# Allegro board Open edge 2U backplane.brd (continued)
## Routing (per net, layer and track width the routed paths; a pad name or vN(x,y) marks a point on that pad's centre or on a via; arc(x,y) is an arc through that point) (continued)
SMB_SLED_COMBINE_SCL_R1: length 15.9
  TOP w0.114: R4.2 167.08,25.94 v1(167.58,25.44)
  IN2 w0.127: v1(167.58,25.44) 168.08,25.94 170.46,25.94 171.54,27.02 179.21,27.02 179.98,27.79 J8.G5
SMB_SLED_COMBINE_SDA: length 149.5
  TOP w0.114: v1(34.53,30.39) 33.08,28.94 33.08,21.74 R1122.2 ; R5.1 164.46,27.03 v1(163.5,27.99) ; R47.1 v1(153.02,31.64)
  IN1 w0.127: v1(34.53,30.39) 35.42,31.28 35.42,32.95 38.78,36.31 147.69,36.31 152.35,31.64 v1(153.02,31.64)
  IN2 w0.127: v1(153.02,31.64) 153.37,31.3 160.2,31.3 v1(163.5,27.99)
SMB_SLED_COMBINE_SDA_R: length 4.5
  TOP w0.114: R49.2 R47.2 154.69,30.77 155.6,30.77 156.29,30.08 U118.6
SMB_SLED_COMBINE_SDA_R1: length 16.1
  TOP w0.114: R5.2 166.8,27.03 167.26,27.49 v1(167.7,27.49)
  IN2 w0.127: J8.H5 180.27,29.19 179.66,29.79 171.6,29.79 169.31,27.49 v1(167.7,27.49)
TMP75_1_A0: length 5.9
  TOP w0.114: U31.7 38.91,27.21 v3(38.13,27.98) 37.84,28.28 R1114.1 R1113.2
TMP75_1_A1: length 5.4
  TOP w0.114: U31.6 v3(40.18,27.72) 40.18,29.69 R1108.2 R1109.1
TMP75_1_A2: length 6.1
  TOP w0.114: U31.5 41.45,26.4 42.31,27.27 42.31,28.42 41.59,29.15 R1102.2 R1103.1
TP_BUF_EN: length 4.4
  TOP w0.114: 154.42,33.64 155.29,32.77 155.29,32.01 156.49,30.81 U118.5
TP_FM_BMC_SLED4_READY_N: length 5.3
  BOTTOM w0.114: v2(176.91,38.11) 177.62,37.4 177.62,34.1 J8.K3
TP_FM_BMC_SLED5_READY_N: length 9.5
  BOTTOM w0.114: v2(195.35,32.52) 190.46,32.52 189.89,31.95 189.89,31.52 189.6,31.23 188.43,31.23 187.68,30.49 J8.I8
TP_FM_SLED4_PRSNT_N: length 9.5
  BOTTOM w0.114: J8.J3 177.6,31.98 177.89,32.27 177.89,37.26 178.73,38.11 v2(180.91,38.11)
TP_FM_SLED5_PRSNT_N: length 8.4
  BOTTOM w0.114: v2(194.01,30.51) 193.32,31.2 190.13,31.2 189.76,30.84 189.76,30.6 189.11,29.95 188.23,29.95 187.37,29.09 J8.H8
TP_LAN_SLED4_MDIN0: length 3.2
  BOTTOM w0.114: J8.H1 170.06,29.19 v2(169.79,29.46)
TP_LAN_SLED4_MDIN1: length 3
  BOTTOM w0.114: J8.K1 v2(169.91,33.38)
TP_LAN_SLED4_MDIN2: length 9.1
  TOP w0.114: v3(169.44,35.64) 170.5,35.64 171.69,34.44 171.69,31.92 172.29,31.32 174.06,31.32 J8.I2
TP_LAN_SLED4_MDIN3: length 6.8
  TOP w0.114: J8.L2 171.62,37.97 v3(169.45,37.97)
TP_LAN_SLED4_MDIP0: length 3.2
  BOTTOM w0.114: J8.G1 171.8,27.79 171.61,27.59 v2(169.79,27.59)
TP_LAN_SLED4_MDIP1: length 3.2
  BOTTOM w0.114: v2(169.89,31.41) 170.46,31.98 J8.J1
TP_LAN_SLED4_MDIP2: length 8.1
  TOP w0.114: J8.H2 174.09,29.9 172.03,29.9 171.09,30.84 171.09,31.98 v3(169.4,33.66)
TP_LAN_SLED4_MDIP3: length 9.3
  TOP w0.114: J8.K2 174,34.19 174,34.83 171.9,36.93 v3(167.44,36.93)
TP_LAN_SLED5_MDIN0: length 13.2
  IN1 w0.127: J8.K5 179.87,33.38 179.27,33.99 172.13,33.99 171.32,34.79 169.11,34.79 v1(168.54,34.22)
TP_LAN_SLED5_MDIN1: length 20.4
  BOTTOM w0.114: v2(200.51,36.24) 199.18,37.57 186.39,37.57 183.77,34.95 183.77,34.15 J8.K6
TP_LAN_SLED5_MDIN2: length 16.7
  BOTTOM w0.114: J8.K7 185.67,34.16 185.67,36.04 186.93,37.3 197.43,37.3 v2(198.47,36.27)
TP_LAN_SLED5_MDIN3: length 10.8
  BOTTOM w0.114: J8.L8 189.25,37.04 195.74,37.04 v2(196.45,36.33)
TP_LAN_SLED5_MDIP0: length 13.7
  IN1 w0.127: J8.J5 180.13,31.98 179.52,32.59 v1(167.45,32.59)
TP_LAN_SLED5_MDIP1: length 17.7
  IN1 w0.127: v1(166.29,34.62) 167.1,35.43 179.17,35.43 180.48,34.13 181.38,34.13 181.93,34.68 J8.L6
TP_LAN_SLED5_MDIP2: length 11.9
  BOTTOM w0.114: J8.J7 185.81,31.98 186.4,32.57 187.58,32.57 187.98,32.96 187.98,33.82 188.29,34.14 189.57,34.14 189.98,34.55 189.98,35.19 190.28,35.49 192.72,35.49 v2(193.95,34.26)
TP_LAN_SLED5_MDIP3: length 9.2
  BOTTOM w0.114: J8.K8 186.9,33.28 187.88,34.27 187.88,35.15 189.5,36.77 193.23,36.77 v2(193.84,36.16)
TP_TMP75_1_ALERT: length 5.1
  TOP w0.114: U31.3 40.18,19.46 40.89,18.74 v1(44.39,18.74)

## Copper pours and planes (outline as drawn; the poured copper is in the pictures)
GND on TOP (solid shape): 244.9,2.05 236.9,2.05 236.9,4.05 244.9,4.05
GND on TOP (solid shape): 36.08,65.24 36.58,65.24 36.58,65.24 37.26,65.24 37.36,65.15 37.36,47.64 37.18,47.46 32.37,47.46 31.75,48.08 31.75,64.66 32.33,65.24 36.08,65.24
GND on TOP (solid shape): 149.84,10.79 152.29,10.79 152.36,10.73 157.64,10.73 157.7,10.79 160.85,10.79 160.85,10.29 149.82,10.29 149.48,10.43 149.34,10.77 149.34,17.8 118.06,17.8 118.06,18.31 149.84,18.31
GND on TOP (solid shape): 164.76,37.7 164.76,33.98 164.59,33.81 156.71,33.81 156.65,33.87 156.65,34.79 156.54,34.9 153.42,34.9 150.85,32.34 150.85,32.33 150.56,32.04 150.56,30.84 150.18,30.46 150.17,30.45 149.95,30.32 149.87,30.08 149.98,29.81 150.25,29.7 150.33,29.71 150.42,29.74 150.51,29.73 150.56,29.65 150.56,18.66 149.81,17.91 144.17,17.91 144.01,18.06 144.01,37.47 144.81,38.26 164.2,38.26
GND on TOP (solid shape): 171.34,18.17 192.08,18.17 192.21,18.3 194.87,18.3 194.87,10.79 201.69,10.79 201.79,10.7 207.72,10.7 207.82,10.79 218.6,10.79 219.12,10.73 219.6,10.53 220.65,10.53 220.94,10.23 220.94,9.18 220.85,9.08 220.08,9.08 219.55,9.95 218.6,10.29 194.85,10.29 194.5,10.43 194.36,10.77 194.36,17.8 169.94,17.8 169.94,18.3 171.2,18.3
GND on TOP (solid shape): 256.9,72.25 256.9,2.06 256.46,1.62 249.7,1.62 249.63,1.7 249.63,29.1 252.83,33.85 249.63,38.6 249.63,72.51 249.76,72.64 256.51,72.64
GND on TOP (solid shape): outline of 303 points within 0.15,64 11.15,71.5
GND on TOP (solid shape): outline of 303 points within 32.15,11 43.15,18.5
GND on TOP (solid shape): outline of 303 points within 96.15,11 107.15,18.5
GND on TOP (solid shape): outline of 303 points within 149.15,11 160.15,18.5
GND on TOP (solid shape): outline of 303 points within 199.15,11 210.15,18.5
GND on TOP (solid shape): outline of 303 points within 220.15,64 231.15,71.5
GND on TOP (solid shape): outline of 132 points within 0.51,0.51 256.99,72.69
GND on BOTTOM (solid shape): 189.22,17.8 169.94,17.8 169.94,18.3 189.22,18.3
GND on BOTTOM (solid shape): 244.9,2.05 236.9,2.05 236.9,4.05 244.9,4.05
GND on BOTTOM (solid shape): 149.84,10.79 152.29,10.79 152.36,10.73 157.64,10.73 157.71,10.79 160.85,10.79 160.85,10.29 149.82,10.29 149.48,10.43 149.34,10.77 149.34,17.8 118.06,17.8 118.06,18.31 149.84,18.31
GND on BOTTOM (solid shape): 256.95,72.2 256.95,2.07 256.55,1.67 251.14,1.67 251.14,30.04 252.39,31.77 252.83,33.85 252.39,35.93 251.14,37.66 251.14,72.05 250.86,72.33 250.86,72.48 250.98,72.6 256.56,72.6
GND on BOTTOM (solid shape): 194.87,10.79 201.69,10.79 201.79,10.69 207.72,10.69 207.82,10.79 218.6,10.79 219.12,10.73 219.6,10.53 220.65,10.53 221.04,10.14 221.04,9.27 220.85,9.08 220.08,9.08 219.55,9.95 218.6,10.29 194.85,10.29 194.5,10.43 194.36,10.77 194.36,17.8 193.97,17.8 193.97,18.3 194.87,18.3
GND on BOTTOM (solid shape): outline of 303 points within 0.15,64 11.15,71.5
GND on BOTTOM (solid shape): outline of 303 points within 32.15,11 43.15,18.5
GND on BOTTOM (solid shape): outline of 303 points within 96.15,11 107.15,18.5
GND on BOTTOM (solid shape): outline of 303 points within 149.15,11 160.15,18.5
GND on BOTTOM (solid shape): outline of 303 points within 199.15,11 210.15,18.5
GND on BOTTOM (solid shape): outline of 303 points within 220.15,64 231.15,71.5
GND on BOTTOM (solid shape): outline of 3515 points within 0.51,0.51 256.99,72.69
GND on GND (solid shape): outline of 2466 points within 0.51,0.51 256.99,72.69
GND on IN1 (solid shape): 149.84,10.79 165.13,10.79 165.13,10.29 149.82,10.29 149.48,10.43 149.34,10.77 149.34,17.8 118.06,17.8 118.06,18.31 149.84,18.31
GND on IN1 (solid shape): 194.87,10.79 218.6,10.79 219.12,10.73 219.6,10.53 220.65,10.53 221.04,10.14 221.04,9.27 220.85,9.08 220.08,9.08 219.55,9.95 218.6,10.29 194.85,10.29 194.5,10.43 194.36,10.77 194.36,17.8 169.97,17.8 169.97,18.3 194.87,18.3
GND on IN1 (solid shape): outline of 125 points within 0.51,0.51 256.99,72.69
GND on IN1 (solid shape): outline of 2408 points within 0.64,10.39 46.58,72.59
GND on IN1 (solid shape): outline of 3747 points within 189.33,0.67 256.92,72.59
GND on IN2 (solid shape): 189.2,17.8 169.97,17.8 169.97,18.3 189.2,18.3
GND on IN2 (solid shape): 149.84,10.79 165.13,10.79 165.13,10.29 149.82,10.29 149.48,10.43 149.34,10.77 149.34,17.8 118.07,17.8 118.07,18.31 149.84,18.31
GND on IN2 (solid shape): 194.87,10.79 218.6,10.79 219.12,10.73 219.6,10.53 220.65,10.53 221.04,10.14 221.04,9.27 220.85,9.08 220.08,9.08 219.55,9.95 218.6,10.29 194.85,10.29 194.5,10.43 194.36,10.77 194.36,17.8 192.8,17.8 192.8,18.3 194.87,18.3
GND on IN2 (solid shape): 256.95,72.24 256.95,2.31 256.29,1.65 236.72,1.65 236.69,1.68 236.69,1.78 236.74,1.83 237.06,1.83 237.62,2.39 237.62,3.89 238.45,4.72 239.1,4.72 239.1,4.72 250.07,4.72 250.21,4.72 251.02,5.54 251.02,29.94 252.83,33.85 251.02,37.76 251.02,71.93 250.66,72.28 250.66,72.47 250.81,72.62 251.02,72.62 251.04,72.64 256.54,72.64
GND on IN2 (solid shape): outline of 129 points within 0.51,0.51 256.99,72.69
GND on IN2 (solid shape): outline of 7125 points within 0.57,10.35 161.7,72.58
GND on GND1 (solid shape): outline of 2466 points within 0.51,0.51 256.99,72.69
P3V3_RMC_STBY on TOP (solid shape): 166.85,33.05 166.85,32.13 166.59,31.87 166.02,31.87 165.84,32.05 165.84,32.3 165.82,32.43 165.76,32.55 165.74,32.62 165.68,32.67 165.67,32.67 165.49,32.85 163.45,32.85 162.58,31.98 162.58,31.47 162.43,31.31 161.52,31.31 161.45,31.31 161.37,31.29 160.74,31.29 160.63,31.17 160.63,29.21 160.75,29.09 161.25,29.09 161.38,29.02 161.52,28.99 162.4,28.99 162.43,28.97 162.43,27.02 162.18,26.77 161.12,26.77 161.07,26.82 161.07,27.06 161.07,27.07 161.13,27.2 161.15,27.34 161.13,27.49 161.07,27.62 161.07,27.63 161.07,27.77 160.83,28.01 157.87,28.01 157.59,27.72 157.59,27.53 157.56,27.44 157.56,27.35 157.56,27.27 157.59,27.18 157.59,27.05 157.57,27.03 157.57,26.79 157.28,26.5 154.18,26.5 153.93,26.74 153.93,28.37 154.01,28.45 156.07,28.45 156.62,28.99 157.17,28.99 157.32,29.02 157.45,29.09 157.76,29.09 157.79,29.09 157.84,29.11 158.44,29.71 158.44,31.18 158.06,31.56 156.25,31.56 155.66,32.15 155.66,33.07 156.01,33.41 166.49,33.41
P3V3_RMC_STBY on BOTTOM (solid shape): 180.27,34.87 180.27,32.82 179.9,32.46 178.43,32.46 178.22,32.67 178.22,35.12 178.38,35.29 179.85,35.29
P12V_PSU on TOP (solid shape): outline of 1544 points within 221.54,4.44 249.27,71.67
P12V_PSU on TOP (solid shape): outline of 2498 points within 21.93,18.69 143.72,66.38
P12V_PSU on BOTTOM (solid shape): outline of 1671 points within 221.47,4.61 250.75,71.87
P12V_PSU on IN1 (solid shape): outline of 1458 points within 221.47,4.86 250.27,65.18
P12V_PSU on IN1 (solid shape): outline of 2640 points within 21.21,18.6 143.94,65.03
P12V_PSU on VCC (solid shape): outline of 4546 points within 1.02,1.02 256.48,72.18
P12V_PSU on VCC1 (solid shape): outline of 4557 points within 1.02,1.02 256.48,72.18
P12V_PSU on IN2 (solid shape): outline of 1631 points within 221.47,4.98 250.75,71.75

Small or netless copper shapes (teardrops, artwork), in the pictures only: 2 on IN1

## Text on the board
User.Comments: Baseboard Rev.3A | TEL:(03)327-2345 FAX:(03)397-3614 | PROJECT: | P/N: | DATE: | LIB: | REV: | Tool: | NO.188,WEN HWA 2ND RD. | KUEI SHAN HSIANG,TAO YUAN | SHIEN,TAIWAN R.O.C. | Layer | HU GAO | S9NQ_2U_Middle_Plane_BD | DAS9NQIB8A0 | 2019/07/08 | 16.6 | 17.2 | A | Quanta | F
Ref Des/Silkscreen Top: SLED1/BBU | P/N:DAS9NQIB8A0 | SLED2 | SLED3 | Rev:A
User.18: 2.3 | 53 | 73.2 | 64.1 | 1.4 | 9.2 | 43.95 | 35.55 | 32.29 | 31.85 | 21.55 | 19.39 | 18.78 | 0 | 33.85 | 10.95 | 17.4 | 23 | 25.05 | 49.9 | 67.9 | 85.9 | 110.9 | 120.9 | 138.9 | 163.9 | 172.9 | 223.7 | 230.95 | 237.4 | 245.05 | 247.7 | 257.5
User.20: 246.15 | 232.05 | 207.6 | 189.6 | 171.6 | 136.6 | 118.6 | 84.6 | 33.8 | 26.95 | 12.85 | 0 | 64.4 | 44.25 | 35.55 | 21.75 | 1.6 | 32.29 | 19.39
User.22: {\Fgdt;n}\Ftxt;4.9 | {\Fgdt;n}\Ftxt;7.5 | {\Fgdt;n}\Ftxt;2.1 | {\Fgdt;n}\Ftxt;2.65 | {\Fgdt;n}\Ftxt;3.5 | {\Fgdt;n}\Ftxt;5.16 | {\Fgdt;n}\Ftxt;10 | 73.2 | 39.6 | 17.29 | 0 | 9.78 | 1.05 | {\Fgdt;n}\Ftxt;5.6 | 9.5 | 8.3 | 2 | 8 | 257.5 | {\Fgdt;n}\Ftxt;2.7 | 3.5 | 219.6 | 193.53 | 161.68 | 140.53 | 1.64 | 108.68 | 87.55 | 63.65 | 43.5 | 25.6 | 2.3
User.23: 253.6 | 239.72 | 234.5 | 221.6 | 186.6 | 168.6 | 157.6 | 145.1 | 133.6 | 115.6 | 104.6 | 92.1 | 54.6 | 33.6 | 20.52 | 9.8 | 0 | 67.75 | 53.3 | 33.85 | 31.85 | 21.29 | 15.28 | 14.75 | 10.65
User.24: 6 | 3 | 2 | 8 | 5 | 4 | 7 | 1 | 9
User.26: 253.6 | 239.72 | 234.5 | 221.6 | 186.6 | 168.6 | 157.6 | 145.1 | 133.6 | 115.6 | 104.6 | 92.1 | 54.6 | 33.6 | 20.52 | 9.8 | 0 | 67.75 | 53.3 | 33.85 | 31.85 | 21.29 | 15.28 | 14.75 | 10.65
User.27: 246.15 | 232.05 | 207.6 | 189.6 | 171.6 | 136.6 | 118.6 | 84.6 | 33.8 | 26.95 | 12.85 | 0 | 64.4 | 44.25 | 35.55 | 21.75 | 1.6 | 32.29 | 19.39
User.28: {\Fgdt;n}\Ftxt;4.9 | {\Fgdt;n}\Ftxt;7.5 | {\Fgdt;n}\Ftxt;2.1 | {\Fgdt;n}\Ftxt;5.16 | {\Fgdt;n}\Ftxt;10 | {\Fgdt;n}\Ftxt;5.6 | 73.2 | 39.6 | 17.29 | 0 | 9.78 | 1.05 | 1.64 | R0.5 | {\Fgdt;n}\Ftxt;3.5 | {\Fgdt;n}\Ftxt;2.65 | 3.5 | 9.5 | 2 | 8 | 11.5 | 12.15 | 9 | {\Fgdt;n}\Ftxt;2.7 | 257.5 | 219.6 | 193.53 | 161.68 | 8.3 | 140.53 | 108.68 | 87.55 | 63.65 | 43.5 | 25.6 | 2.3 | {\Fgdt;n}\Ftxt;7.16 | 3.64 | R1.5 | 1.5 | {\Fgdt;n}\Ftxt;7
User.29: 246.15 | 232.05 | 207.6 | 189.6 | 171.6 | 136.6 | 118.6 | 84.6 | 33.8 | 26.95 | 12.85 | 0 | 64.4 | 44.25 | 35.55 | 21.75 | 1.6 | 32.29 | 19.39
User.31: {\Fgdt;n}\Ftxt;2.1 | {\Fgdt;n}\Ftxt;4.9 | {\Fgdt;n}\Ftxt;7.5 | {\Fgdt;n}\Ftxt;5.16 | {\Fgdt;n}\Ftxt;10 | 73.2 | 39.6 | 17.29 | 0 | 9.78 | 1.05 | {\Fgdt;n}\Ftxt;5.6 | 1.64 | R0.5 | {\Fgdt;n}\Ftxt;3.5 | {\Fgdt;n}\Ftxt;2.65 | 3.5 | 9.5 | 2 | 8 | 11.5 | 12.15 | 9 | 257.5 | 219.6 | 193.53 | {\Fgdt;n}\Ftxt;2.7 | 161.68 | 140.53 | 108.68 | 87.55 | 63.65 | 8.3 | 43.5 | 25.6 | {\Fgdt;n}\Ftxt;7.16 | 3.64 | R1.5 | 1.5 | {\Fgdt;n}\Ftxt;7.6
User.32: 253.6 | 239.72 | 234.5 | 221.6 | 186.6 | 168.6 | 157.6 | 145.1 | 133.6 | 115.6 | 104.6 | 92.1 | 54.6 | 33.6 | 20.52 | 9.8 | 0 | 67.75 | 53.3 | 33.85 | 31.85 | 21.29 | 15.28 | 14.75 | 10.65
User.33: TOP | 1
User.34: BOTTOM | 8
User.35: SILK-TOP
User.36: SILK-BOT
User.37: MASK-TOP
User.38: MASK-BOT
User.39: FAB
User.40: PAST-TOP
User.41: PAST-BOT
User.42: GND | 2
User.43: VCC | 4
User.44: IN1 | 3
User.45: MARK:TIN LEAD:RECOMMENDED DRILL SIZE FOR 0.5MM FINISHED PTH IS 0.6MM METRIC DRILL OR #74 ENGLISH DRILL.(0.57~0.61) | O:RECOMMENDED DRILL SIZE FOR 0.5MM FINISHED PTH IS 0.6MM METRIC DRILL OR #74 ENGLISH DRILL. | TIN-LEAD:RECOMMENDED DRILL SIZE FOR 0.725MM FINISHED PTH IS 0.81-0.86MM(0.85MM DRILL) | IMMERSION TIN/IMMERSION SILVER/COPPER:RECOMMENDED DRILL SIZE FOR 0.75MM FINISHED PTH IS 0.81-0.86MM(0.85MM DRILL). | GOLD:RECOMMENDED DRILL SIZE FOR 0.745MM FINISHED PTH IS 0.81-0.86MM(0.85MM DRILL) | NON-MARK:RECOMMENDED DRILL SIZE FOR 0.4MM FINISHED PTH IS 0.5MM METRIC DRILL OR #77 ENGLISH DRILL. | NON-MARK:TIN LEAD:RECOMMENDED DRILL SIZE FOR 0.4MM FINISHED PTH IS 0.5MM METRIC DRILL OR #77 ENGLISH DRILL.(0.47~0.51) | COPPER OSP/TIN(IMMERSION):RECOMMENDED DRILL SIZE FOR 0.5MM FINISHED PTH IS 0.6MM METRIC DRILL OR #74 ENGLISH DRILL.(0.54~0.6) | SILVER(IMMERSION):RECOMMENDED DRILL SIZE FOR 0.5MM FINISHED PTH IS 0.6MM METRIC DRILL OR #74 ENGLISH DRILL.(0.54~0.6) | COPPER OSP/TIN(IMMERSION):RECOMMENDED DRILL SIZE FOR 0.4MM FINISHED PTH IS 0.5MM METRIC DRILL OR #77 ENGLISH DRILL.(0.44~0.5) | SILVER(IMMERSION):RECOMMENDED DRILL SIZE FOR 0.4MM FINISHED PTH IS 0.5MM METRIC DRILL OR #77 ENGLISH DRILL.(0.44~0.5) | PANEL | GND1 | IN2 | IN3 | IN4 | VCC1 | 5 | 6 | 7 | FIGURE | FINISHED_SIZE | 10.0 | 15.74 | 19.68 | 29.52 | 138.0 | 204.0 | 221.0 | 85.0 | 105.0 | 107.0 | 125.0 | DRILL CHART: TOP to BOTTOM | ALL UNITS ARE IN MILS | TOLERANCE_DRILL | +0.0/-10.0 | +1.96/-1.96 | +3.0/-3.0 | +2.0/-2.0 | +2.0/-0.0 | PLATED | NON-PLATED | QTY | 52 | 192 | 206 | 81 | 214 | 2 | 3 | 4
